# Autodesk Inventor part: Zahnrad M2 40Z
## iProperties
Created: 2006-11
Part Number: Zahnrad M2 40Z
Cost Center: 0,777 kg
Material: Stahl (schweißbar)
Document SubType Name: Modeling
Designer: Schmidt
Authority: 98819 mm^3
Density: 7.86 g/cm^3
SaveDate: 2006-11-07
SaveTime: 19:52
TotalMass: 0,777 kg
TotalVolume: 98819 mm^3
Author: Schmidt
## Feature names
1. Basis1
2. Bohrung2 [Hole]
3. Bohrung3 [Hole]
4. Extrusion2
